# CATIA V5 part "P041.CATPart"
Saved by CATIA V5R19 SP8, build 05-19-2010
Part number: 05-LICP-T02-E-S03-P041
Definition: Graisseur standard droit
Description: Graisseur standard droit - M6 x 100 court
Property "REFERENCE": "9 20 00 02"
Property "SUPPLIER": "TECALEMIT EQUIPEMENTS"
Property "AUTHOR": "Trace Parts S.A."
Property "WEB": "www.traceparts.com"
Bounding box of the stored display mesh (mm): x -3.5 to 3.5, y -3 to 10.368, z -4.041 to 4.041
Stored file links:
  L:\CONCEPTION\CAO GMP1   2013 -  2014\S 2\PRESSE MECANIQUE\PRESSE_MECA_PENNEC\05-LICP-T02-E-S03-P041.CATPart
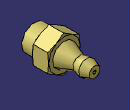
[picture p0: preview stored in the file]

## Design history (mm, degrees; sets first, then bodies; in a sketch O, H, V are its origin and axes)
Body1 (main body)
  Solid1: solid without history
